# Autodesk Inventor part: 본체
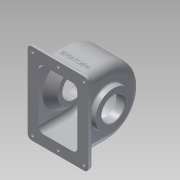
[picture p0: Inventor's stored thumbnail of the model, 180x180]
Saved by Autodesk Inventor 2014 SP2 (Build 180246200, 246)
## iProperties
Created: 2015-09
Part Number: 본체
Material: 알루미늄 6061
Document SubType Name: Modeling
Designer: 201-24
Density: 2.71 g/cm^3
Appearance: 알루미늄 - 평지
Mass: 722.104 g
Surface Area: 895.877 cm^2
Volume: 266.459 cm^3
Author: 201-24
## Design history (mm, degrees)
sketch "스케치1"
  geometry: L1 (-52, -70)-(52, -70); L2 (52, -70)-(52, 70); L3 (52, 70)-(-52, 70); L4 (-52, 70)-(-52, -70); L5 (-52, -70)-(52, 70); L6 (52, -70)-(-52, 70); 1 further point
  constraints: 12 end point, 2 midpoint, 2 parallel, 1 horizontal, 1 perpendicular
  dimensions: "d0" = 104 distance of L2.end L3.end; "d1" = 140 distance of L1.end L2.end
extrude "돌출1" new body sketch "스케치1" distance "d2" = 7; taper "d3" = 0 deg
sketch "스케치3"
  geometry: L1 (-29.846, 0)-(179.075, 0) reference; L2 (7, 70)-(7, -70) reference; L3 (47, 57)-(7, 57); L4 (47, -57)-(7, -57); A1 r 57 centre (47, 0) between (7, 40.608) and (7, -40.608); A2 r 57 centre (47, 0) between (47, 57) and (7, 40.608); A3 r 57 centre (47, 0) between (7, -40.608) and (47, -57); A4 r 57 centre (47, 0) between (47, -57) and (47, 57); 1 further point
  constraints: 9 point on circle, 6 tangent, 5 point on line, 4 centre point, 4 end point, 2 perpendicular
  dimensions: "d4" = 114 diameter of A1; "d5" = 40 distance from line of L2 A1.centre
extrude "돌출2" join sketch "스케치3" stored distance "d6" = 77; taper "d7" = 0 deg
fillet "모깎기1" dims "d8" = 14
sketch "스케치4"
  geometry: L1 (47, -57)-(7, -57) reference; L2 (7, 57)-(47, 57) reference; L3 (7, 51)-(47, 51); L4 (47, -51)-(7, -51); L5 (0, -70)-(0, 70) reference; L6 (7, 51)-(0, 51); L7 (7, -51)-(0, -51); A1 r 57 centre (47, 0) between (47, -57) and (47, 57) reference; A2 r 51 centre (47, 0) between (47, -51) and (47, 51); 1 further point
  constraints: 8 end point, 2 perpendicular, 2 point on circle, 2 point on line, 1 centre point, 2 other
  dimensions: "d9" = 6 radial gap between concentric circles of A1 A2
extrude "돌출3" cut sketch "스케치4" stored distance "d10" = 67; taper "d11" = 0 deg
fillet "모깎기2" dims "d12" = 9
fillet "모깎기3" dims "d13" = 7
sketch "스케치5"
  geometry: C1 r 31 at (0, 47); A1 r 43 centre (0, 47) between (43, 47) and (-43, 47) reference; 1 further point
  constraints: 1 centre point, 1 concentric
  dimensions: "d14" = 62 diameter of C1
extrude "돌출4" join sketch "스케치5" distance "d15" = 10; taper "d16" = 0 deg
sketch "스케치6"
  geometry: C1 r 28 at (0, 47); A1 r 42 centre (0, 47) between (42, 47) and (-42, 47) reference; 1 further point
  constraints: 1 centre point, 1 concentric
  dimensions: "d17" = 56 diameter of C1
extrude "돌출5" join sketch "스케치6" distance "d18" = 14; taper "d19" = 0 deg
chamfer "모따기2" distance "d23" = 14; stored, may be unused: second distance "d24" = 2, angle "d25" = 40 deg
sketch "스케치8"
  geometry: L1 (-19.5, 75)-(-33.5, 86.747) reference; L2 (-19.5, 19)-(-33.5, 7.253) reference; L3 (-19.5, 19)-(-19.5, 75) reference; L4 (-38.5, 47)-(-38.5, 90) reference; L5 (-38.5, 7)-(-38.5, 47) reference; L6 (-38.5, 84.416)-(-24.5, 72.668); L7 (-24.5, 72.668)-(-24.5, 47); L8 (-24.5, 21.332)-(-38.5, 9.584); L9 (-19.5, 47)-(-38.5, 47); L10 (-24.5, 47)-(-24.5, 21.332); L11 (-38.5, 47)-(-38.5, 84.416); 1 further point
  constraints: 12 end point, 3 point on line, 2 perpendicular, 1 midpoint, 1 parallel
  dimensions: "d26" = 5 distance between parallel lines of L1 L6; "d27" = 5 distance between parallel lines of L2 L8; "d28" = 5 distance between parallel lines of L3 L7
revolve "회전1" sketch "스케치8" stored, may be unused: angle "d29" = 90 deg
node "작업 평면1"
sketch "스케치10"
  geometry: C1 r 33 at (0, 47); C2 r 25.668 at (0, 47) reference; 1 further point
  constraints: 1 centre point, 1 concentric
  dimensions: "d31" = 66 diameter of C1
extrude "돌출6" join sketch "스케치10" stored distance "d32" = 14; taper "d33" = 0 deg
hole "구멍1" diameter "d36" = 40; stored, may be unused: countersink angle "d40" = 90 deg, drill point angle "d42" = 0 deg; dims "d37" = 6, "d38" = 4, "d39" = 2, "d41" = 8, "d43" = 10, "d44" = 10
sketch "스케치11"
  geometry: C1 r 20 at (0, 0) reference; 2 further points
  constraints: 1 vertical alignment
  dimensions: "d45" = 28 distance of C1.centre point (0, 28)
hole "구멍2" sketch "스케치11" at (0, 28) diameter "d46" = 2.459; stored, may be unused: countersink angle "d50" = 90 deg, drill point angle "d52" = 118 deg; dims "d47" = 7, "d48" = 4, "d49" = 2, "d51" = 9
sketch "스케치12"
  geometry: C1 r 20 at (0, 0) reference; 2 further points
  constraints: 1 vertical alignment
  dimensions: "d56" = 24 distance of C1.centre point (0, 24)
hole "구멍3" sketch "스케치12" at (0, 24) diameter "d57" = 2.459; stored, may be unused: countersink angle "d61" = 90 deg, drill point angle "d63" = 118 deg; dims "d58" = 6, "d59" = 4, "d60" = 2, "d62" = 8
node "작업 평면2"
sketch "스케치16"
  geometry: L1 (104, 0)-(110, 0); L2 (110, 0)-(110, 6); L3 (110, 6)-(103.551, 7.137); A1 r 57 centre (47, 0) between (47, -57) and (47, 57) reference; 1 further point
  constraints: 6 end point, 2 point on circle, 1 horizontal, 1 perpendicular
  dimensions: "d78" = 6 distance of L1.start L1.end; "d79" = 10 deg angle of L1 L3; "d80" = 6 distance of L1.end L2.end
revolve "회전2" sketch "스케치16" stored, may be unused: angle "d81" = 90 deg
fillet "모깎기5" dims "d82" = 3
hole "구멍4" diameter "d85" = 4.459; stored, may be unused: countersink angle "d89" = 90 deg, drill point angle "d91" = 0 deg; dims "d86" = 20, "d87" = 4, "d88" = 2, "d90" = 20, "d111" = 10, "d112" = 10
sketch "스케치17"
  geometry: L1 (44, -62)-(-44, -62); L2 (-44, -62)-(-44, 62); L3 (-44, 62)-(44, 62); L4 (44, 62)-(44, -62); L5 (44, -62)-(-44, 62); L6 (-44, -62)-(44, 62); 9 further points
  constraints: 12 end point, 5 coincident, 5 midpoint, 2 parallel, 1 horizontal, 1 perpendicular
  dimensions: "d92" = 88 distance of L2.end L3.end; "d93" = 124 distance of L3.end L1.start
hole "구멍5" sketch "스케치17" at (-44, 62), (-44, -62), (44, -62), (44, 62), (0, -62), (0, 62) diameter "d94" = 5; stored, may be unused: countersink angle "d98" = 90 deg, drill point angle "d100" = 118 deg; dims "d95" = 5, "d96" = 4, "d97" = 2, "d99" = 8
fillet "모깎기6" dims "d101" = 3
fillet "모깎기7" dims "d102" = 1
chamfer "모따기4" distance "d103" = 1; stored, may be unused: second distance "d104" = 2, angle "d105" = 10 deg
sketch "스케치18"
  geometry: L1 (-20.5, -47)-(69.5, -47) reference; 3 further points
  constraints: 1 midpoint, 1 vertical alignment, 1 other
  dimensions: "d106" = 30 distance from line of L1 point (24.5, -17)
feature "엠보싱1" sketch "스케치18" dims "d0" = 104, "d1" = 140, "d107" = 0.5, "d108" = 0
fillet "모깎기8" dims "d109" = 3
fillet "모깎기9" dims "d110" = 3
fillet "모깎기10" dims "d113" = 0.5
node "솔리드1"
pattern_circular "원형 패턴1" dims angle "d54" = 360 deg
pattern_circular "원형 패턴2" dims angle "d65" = 360 deg
other parameters: "d30" = -3
